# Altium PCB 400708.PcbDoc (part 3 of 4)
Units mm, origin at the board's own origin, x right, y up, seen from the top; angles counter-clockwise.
Board outline 117 x 63.5 mm, 4 copper layers (Top Layer, Mid-Layer 1, Mid-Layer 2, Bottom Layer), stack 1.556 mm thick; 226 components, 168 nets, 912 pads, 2002 vias.
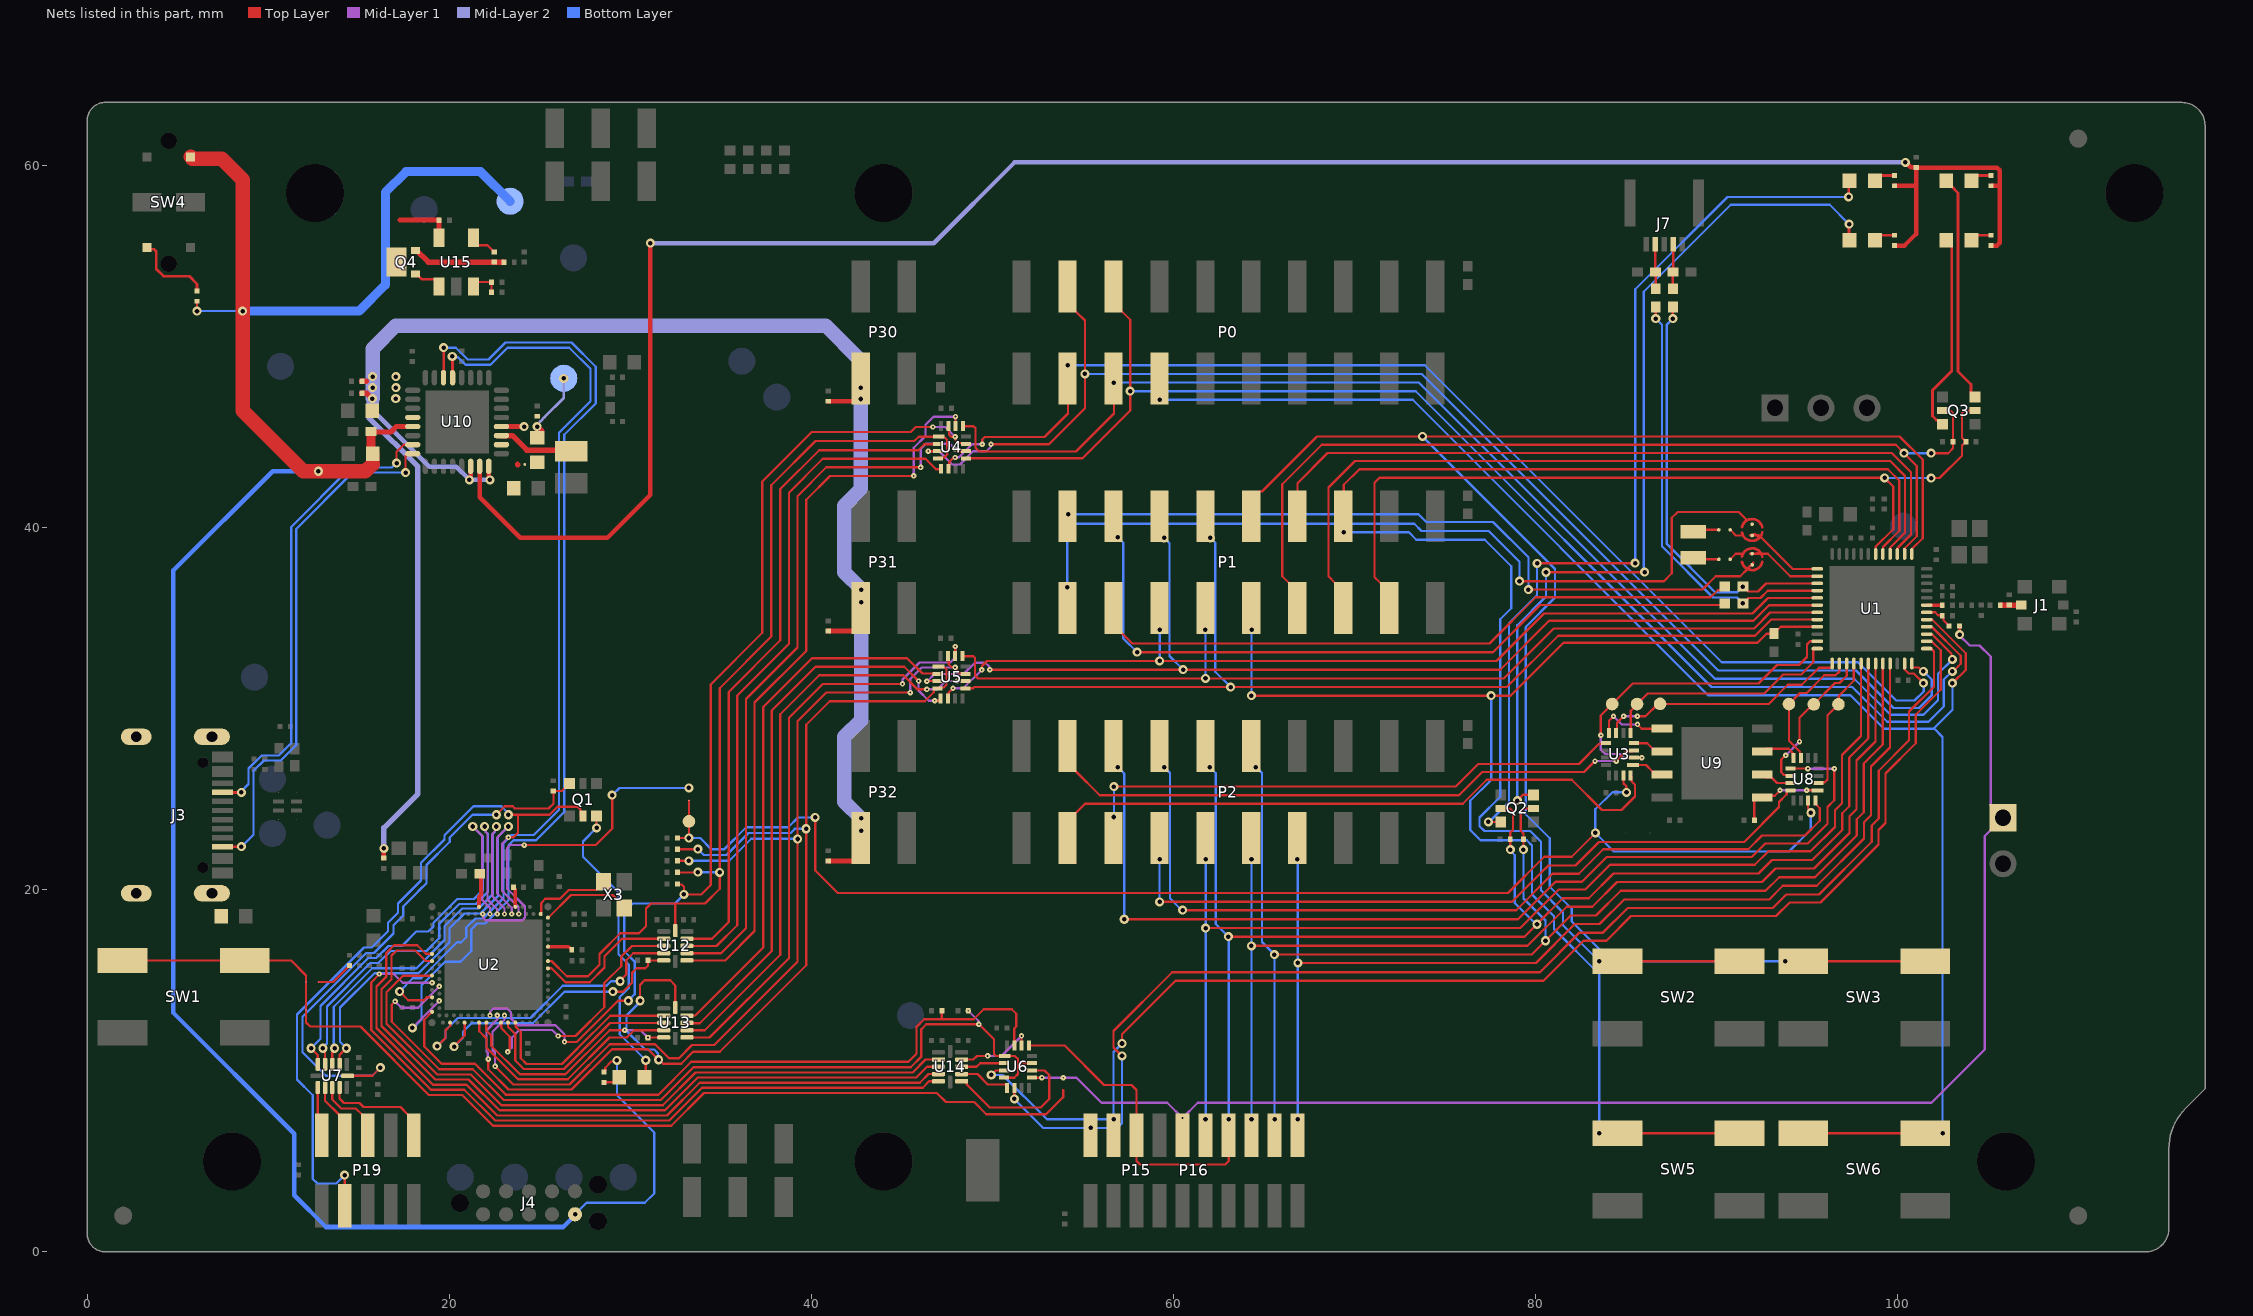
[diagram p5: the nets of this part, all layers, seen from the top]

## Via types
v1: diameter 0.5, hole 0.25, Top Layer to Bottom Layer, tented both sides, 1905 vias
v2: diameter 0.3, hole 0.1, Top Layer to Mid-Layer 1, tented top, 77 vias
v3: diameter 0.3, hole 0.1, Top Layer to Mid-Layer 1, tented both sides, 20 vias

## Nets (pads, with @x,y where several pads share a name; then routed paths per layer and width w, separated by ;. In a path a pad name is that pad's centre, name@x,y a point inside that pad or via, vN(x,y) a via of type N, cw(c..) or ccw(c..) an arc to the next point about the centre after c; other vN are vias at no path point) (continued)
NetC44_1: C44.1 U2.A23 | length 1.1
  Top Layer w0.2: C44.1@23.55,20.154 23.55,20.139 23.66,20.029 U2.A23@23.66,19.064
NetC45_2: C45.2 U2.A13 | length 1.9
  Top Layer w0.225: U2.A13@21.66,19.064 21.66,19.644 21.77,19.754 C45.2@21.77,20.891
NetC59_1: C59.1 J3.SHLD
NetC60_1: C60.1 R3.1 U1.30 | length 1.6
  Top Layer w0.125: U1.30@101.63,35.33 102.102,35.33 102.257,35.175 102.44,35.175 C60.1@102.49,35.125 ; C60.1@102.489,35.117 102.505,35.117 102.561,35.061 102.561,34.99 102.563,34.988 102.563,34.887 R3.1@102.87,34.58
NetC64_2: C64.2 R1.2 R2.2 R19.2 R20.2 U10.31 | length 114.9
  Top Layer w0.25: U10.31@21.692,43.396 21.692,41.686 23.928,39.45 28.749,39.45 31.125,41.826 v1(31.125,55.727) ; R1.2@99.848,55.594 100.403,55.594 101.039,56.23 101.039,58.896 ; R19.2@99.848,58.896 101.039,58.896 ; v1(100.445,60.185) 100.468,60.185 100.743,59.91 101.029,59.91 C64.2@101.039,59.9 ; R2.2@105.182,55.594 105.515,55.594 105.661,55.74 105.661,58.896 ; R20.2@105.182,58.896 105.661,58.896 ; 101.039,58.896 C64.2@101.039,59.9 ; C64.2@101.039,59.9 105.515,59.9 105.661,59.754 105.661,58.896
  Mid-Layer 2 w0.25: v1(31.125,55.727) 46.777,55.727 51.235,60.185 v1(100.445,60.185)
NetC72_1: C72.1 R43.2 U15.3 | length 1.7
  Top Layer w0.125: U15.3@21.35,53.325 21.35,53.338 21.587,53.575 C72.1@22.35,53.575 R43.2@22.35,53.025
NetJ3_A5: J3.A5 U10.23 | length 26.4
  Top Layer w0.125: v1(17.1,43.575) 17.097,43.578 17.097,44.197 17.493,44.593 17.989,44.593 U10.23@17.992,44.596
  Top Layer w0.15: J3.A5@7.485,25.384 v1@8.526,25.384
  Bottom Layer w0.125: v1(8.527,25.383) 8.527,25.451 8.92,25.844 8.92,26.699 9.648,27.428 10.586,27.428 11.275,28.116 11.275,40.046 14.556,43.327 16.839,43.327 17.087,43.575 v1(17.1,43.575)
NetJ3_B5: J3.B5 U10.24 | length 29.1
  Top Layer w0.125: v1(17.594,43.05) 17.591,43.053 17.591,43.935 17.752,44.096 U10.24@17.992,44.096
  Top Layer w0.15: J3.B5@7.485,22.384 v1(8.529,22.384)
  Bottom Layer w0.125: v1(8.529,22.384) 8.538,22.384 9.2,23.046 9.2,26.575 9.775,27.15 10.701,27.15 11.553,28.001 11.553,39.931 14.671,43.05 v1(17.594,43.05)
NetL2_1: L2.1 U1.31 | length 0.9
  Top Layer w0.2: U1.31@101.664,35.73 L2.1@102.521,35.73 ; L2.1@102.521,35.73 L2.1@102.522,35.729
NetL8_2: L8.2 U10.3 | length 4.2
  Top Layer w0.3: U10.3@22.892,45.096 23.492,45.096 24.292,44.296 L8.2@26.749,44.296
NetLD1_1: LD1.1 Q1.6 | length 16.6
  Top Layer w0.125: v1(28.15,23.425) Q1.6@28.15,24.082 ; LD1.1@30.865,9.716 v1(30.865,10.588)
  Top Layer w0.15: LD1.1@30.802,9.652 LD1.1@30.865,9.716
  Bottom Layer w0.125: v1(28.15,23.425) 27.4,22.675 27.4,21.825 29.358,19.867 29.358,16.442 29.925,15.875 29.925,14.575 29.425,14.075 29.425,12.029 v1(30.865,10.588)
NetLD1_2: LD1.2 R5.1 | length 1.4
  Top Layer w0.125: LD1.2@29.12,9.937 LD1.2@29.405,9.652
  Top Layer w0.15: R5.1@28.56,9.367 29.12,9.367 LD1.2@29.405,9.652
NetLD2_1: LD2.1 Q2.6 | length 51.5
  Top Layer w0.125: v1(77.411,23.75) Q2.6@78.1,23.75 ; v1(80.106,38.04) 80.11,38.044 85.519,38.044 v1(85.525,38.05)
  Top Layer w0.15: v1(97.316,58.277) 97.316,59.125 LD2.1@97.371,59.181
  Bottom Layer w0.125: v1(77.411,23.75) 77.45,23.75 78.55,24.85 78.55,34.725 80.106,36.281 v1(80.106,38.04) ; v1(85.525,38.05) 85.525,53.174 90.629,58.278 v1(97.316,58.277)
NetLD2_2: LD2.2 R19.1 | length 1.2
  Top Layer w0.15: LD2.2@98.768,59.181 99.053,59.466 R19.1@99.848,59.466
NetLD3_1: LD3.1 Q3.6 | length 12.6
  Top Layer w0.15: LD3.1@102.705,59.155 103.011,58.849 103.358,58.502 103.358,48.642 104.075,47.925 104.075,47.538 104.076,47.537 104.076,47.449 Q3.6@104.3,47.225
NetLD3_2: LD3.2 R20.1 | length 1.2
  Top Layer w0.15: LD3.2@104.102,59.181 104.387,59.466 R20.1@105.182,59.466
NetLD4_1: LD4.1 Q2.3 | length 49.9
  Top Layer w0.125: v1(79.016,24.934) 79.332,25.25 Q2.3@79.9,25.25 ; v1(80.598,37.544) 86.044,37.544 v1(86.05,37.55)
  Top Layer w0.15: v1(97.341,56.777) 97.341,55.909 LD4.1@97.371,55.879
  Bottom Layer w0.125: v1(79.016,24.934) 79.016,34.618 80.598,36.2 v1(80.598,37.544) ; v1(86.05,37.55) 85.991,37.609 85.991,53.041 90.8,57.85 96.268,57.85 v1(97.341,56.777)
NetLD4_2: LD4.2 R1.1 | length 0.8
  Top Layer w0.15: LD4.2@99.053,56.164 R1.1@99.848,56.164
NetLD5_1: LD5.1 Q3.3 | length 11
  Top Layer w0.15: Q3.3@102.5,45.725 102.275,45.95 102.168,45.95 101.95,46.168 101.95,47.6 103.013,48.663 103.013,55.459 103.011,55.461 103.011,55.573 LD5.1@102.705,55.879
NetLD5_2: LD5.2 R2.1 | length 0.8
  Top Layer w0.15: LD5.2@104.387,56.164 R2.1@105.182,56.164
NetP1_5: P1.5 R33.2 | length 36.7
  Top Layer w0.125: P1.5@56.729,35.877 56.729,34.607 57.734,33.603 77.469,33.603 80.032,36.165 89.69,36.165 90.082,36.557 90.275,36.557 R33.2@90.474,36.755
NetP1_6: P1.6 R34.2 | length 41.6
  Top Layer w0.125: P1.6@56.704,40.64 56.704,39.721 v1(56.95,39.475) ; v1(58.012,33.128) 77.666,33.128 80.268,35.73 90.374,35.73 R34.2@90.474,35.83
  Bottom Layer w0.125: v1(56.95,39.475) 57.25,39.175 57.25,33.89 v1(58.012,33.128)
NetQ1_3: Q1.3 R8.1 U7.12 | length 30.8
  Top Layer w0.125: U7.12@14.4,9.725 15.75,9.725 v1(16.2,10.175) ; v1(22.608,24.15) 23.071,24.613 23.517,24.613 23.641,24.488 25.491,24.488 25.766,24.763 R8.1@25.766,25.449 ; R8.1@25.76,25.455 26.223,25.455 26.477,25.71 Q1.3@26.651,25.71
  Bottom Layer w0.125: v1(16.2,10.175) 15.75,9.725 13.2,9.725 11.9,11.025 11.9,12.983 15.429,16.512 15.848,16.512 16.925,17.589 16.925,18.05 17.462,18.588 17.462,19.081 18.183,19.802 18.371,19.99 18.753,20.372 18.753,21.369 20.043,22.66 20.043,22.893 21.3,24.15 v1(22.608,24.15)
NetQ4_1: Q4.1 U15.1 | length 1.7
  Top Layer w0.15: Q4.1@18.15,54.025 18.2,54.025 18.5,53.725 19.225,53.725 19.45,53.5 U15.1@19.45,53.325
NetQ4_2: Q4.2 R9.1 R38.2 | length 5.1
  Top Layer w0.3: Q4.2@18.15,55.325 18.2,55.325 18.851,54.674 R9.1@23.006,54.674
NetR7_1: R7.1 U2.L31 | length 1.4
  Top Layer w0.187: U2.L31@25.46,16.864 26.597,16.864 26.719,16.743 26.734,16.743 26.775,16.702 R7.1@26.775,16.687
NetR23_1: R23.1 SB8.2 | length 2.1
  Top Layer w0.125: SB8.2@12.8,14.91 13.595,14.91 14.412,15.728 14.412,15.743 14.485,15.815 R23.1@14.5,15.815
NetR35_1: R35.1 SB11.2 TP7.1 U3.15 U8.15 | length 77.3
  Top Layer w0.125: R35.1@32.61,22.864 v1(33.25,22.864) TP7.1@33.25,23.783 SB11.2@33.25,24.933 ; v1(40.225,24) 40.225,21.075 41.478,19.822 78.497,19.822 80.5,21.825 82.025,21.825 83.325,23.125 v1(83.325,23.146) ; U3.15@84.875,26.325 84.875,25.882 85.024,25.733 85.024,25.406 v1(85.044,25.385) ; U8.15@95.075,24.925 95.075,24.506 95.225,24.356 v1(95.225,24.26)
  Bottom Layer w0.125: v1(33.25,22.864) 33.874,22.864 34.502,22.236 35.192,22.236 36.41,23.455 38.737,23.455 39.282,24 v1(40.225,24) ; v1@84.816,25.395 84.27,25.395 83.325,24.45 v1(83.325,23.146) 83.376,23.095 84.346,22.125 94.025,22.125 95.225,23.325 v1(95.225,24.26)
NetR36_1: R36.1 SW4.3 | length 4.5
  Top Layer w0.15: SW4.3@3.321,55.488 3.418,55.392 3.708,55.392 3.825,55.275 3.825,54.3 4.225,53.9 5.646,53.9 6.075,53.471 R36.1@6.075,53.085
NetR38_1: R38.1 U15.4 | length 1.6
  Top Layer w0.125: U15.4@21.35,56.025 21.35,55.825 21.572,55.603 22.126,55.603 R38.1@22.485,55.245
NetSB1_2: SB1.2 SB2.1 SB8.1 SW1.2 | length 59.2
  Top Layer w0.125: SW1.2@1.963,16.097 SW1.2@8.713,16.097 11.277,16.097 12.1,15.273 SB8.1@12.1,14.91 ; 12.1,14.864 SB2.1@12.1,13.364 12.1,12.675 12.325,12.45 15.1,12.45 18.878,8.672 20.728,8.672 22.428,6.972 32.275,6.972 34.086,8.784 46.944,8.784 47.453,8.275 49.011,8.275 49.681,7.605 52.98,7.605 53.925,8.55 SB1.2@53.925,8.925
NetSB3_2: SB3.2 X1.2 | length 1.4
  Top Layer w0.125: X1.2@88.739,39.793 88.833,39.887 SB3.2@90.145,39.887
NetSB4_2: SB4.2 X1.1 | length 1.4
  Top Layer w0.125: X1.1@88.739,38.343 88.82,38.262 SB4.2@90.145,38.262
NetU2_B30: U2.B30 X3.3 | length 4.6
  Top Layer w0.125: U2.B30@25.06,18.664 25.079,18.684 25.079,18.754 25.085,18.76 25.085,19.273 25.315,19.502 26.123,19.502 26.61,19.99 28.127,19.99 28.531,20.394 X3.3@28.531,20.444
NetU2_C31: U2.C31 X3.1 | length 5.1
  Top Layer w0.125: U2.C31@25.46,18.464 25.485,18.464 26.735,19.715 29.027,19.715 29.681,19.061 X3.1@29.681,18.994
NetU4_2: U4.2 U12.10 | length 37.5
  Top Layer w0.125: U12.10@33.14,17.3 34.53,17.3 35.45,18.22 35.45,30.936 38.3,33.786 38.3,42.14 40.45,44.29 45.926,44.29 46.255,44.619 46.984,44.619 U4.2@47.003,44.637
NetU4_5: U4.5 U12.9 | length 37.8
  Top Layer w0.125: U12.9@33.14,16.9 34.775,16.9 35.925,18.05 35.925,30.739 38.775,33.589 38.775,41.944 40.646,43.815 46.322,43.815 46.903,43.233 47.13,43.233 47.16,43.262 U4.5@47.178,43.262
NetU4_10: U4.10 U12.8 | length 40.1
  Top Layer w0.125: U12.8@33.14,16.5 35.016,16.5 36.4,17.884 36.4,30.542 39.25,33.392 39.25,41.747 40.843,43.34 v2@46.05,43.34
  Top Layer w0.127: v2(47.946,44.371) 47.966,44.371 48.1,44.237 U4.10@48.553,44.237
  Mid-Layer 1 w0.125: v2(46.05,43.336) 46.05,44.35 46.341,44.641 47.675,44.641 v2(47.946,44.371)
NetU4_14: U4.14 U12.7 | length 41.4
  Top Layer w0.125: U12.7@33.14,16.1 35.254,16.1 36.875,17.721 36.875,30.346 39.725,33.196 39.725,41.55 41.04,42.865 v2(45.675,42.865) ; U4.14@47.971,45.619 U4.14@47.978,45.612
  Top Layer w0.127: U4.14@47.978,45.612 v2(47.977,46.144)
  Mid-Layer 1 w0.125: v2(45.675,42.865) 45.675,44.425 46.325,45.075 46.325,45.7 46.769,46.144
  Mid-Layer 1 w0.127: 46.769,46.144 v2(47.977,46.144)
NetU5_2: U5.2 U13.10 | length 30.2
  Top Layer w0.125: U13.10@33.14,13.05 33.148,13.058 33.596,13.058 37.35,16.812 37.35,30.101 40.049,32.8 45.3,32.8 46.152,31.948 46.863,31.948 46.875,31.936 U5.2@46.985,31.936
NetU5_5: U5.5 U13.9 | length 31.1
  Top Layer w0.125: U13.9@33.14,12.637 33.847,12.637 37.825,16.616 37.825,29.904 40.246,32.325 45.147,32.325 v2(45.936,31.536) ; v2(46.825,30.45) 47.113,30.45 47.16,30.497 U5.5@47.16,30.561
  Mid-Layer 1 w0.125: v2(45.936,31.536) 45.936,31.014 46.5,30.45 v2(46.825,30.45)
NetU5_10: U5.10 U13.8 | length 31.8
  Top Layer w0.125: U13.8@33.14,12.25 34.131,12.25 38.3,16.419 38.3,29.707 40.443,31.85 45.1,31.85 45.875,31.075 v2(46.4,31.075)
  Top Layer w0.127: v2(48.07,31.536) U5.10@48.535,31.536
  Mid-Layer 1 w0.125: v2(46.4,31.075) 46.975,31.075 47.436,31.536 v2(48.07,31.536)
NetU5_14: U5.14 U13.7 | length 32.6
  Top Layer w0.125: U13.7@33.14,11.84 34.393,11.84 38.775,16.222 38.775,29.51 40.64,31.375 v2(45.05,31.375) ; U5.14@47.953,32.918 U5.14@47.96,32.911
  Top Layer w0.127: U5.14@47.96,32.911 v2@47.96,33.442
  Mid-Layer 1 w0.125: v2(45.05,31.375) 45.05,31.625 45.989,32.564 47.274,32.564 47.275,32.565
  Mid-Layer 1 w0.127: 47.275,32.565 47.69,32.565 47.96,32.835 v2(47.96,33.442)
NetU6_2: U6.2 U14.9 | length 2.4
  Top Layer w0.125: U14.9@48.315,10.225 49.141,10.225 49.341,10.425 U6.2@50.65,10.425
NetU6_5: U6.5 U14.8 | length 2.9
  Top Layer w0.125: U14.8@48.315,9.825 49.189,9.825 49.764,9.25 50.778,9.25 50.825,9.203 U6.5@50.825,9.05
NetU6_10: U6.10 U14.7 | length 8.1
  Top Layer w0.125: U14.7@48.315,9.425 48.536,9.425 48.599,9.363 48.599,9.245 49.864,7.98 51.425,7.98
  Top Layer w0.127: 51.425,7.98 52.682,7.98 53.15,8.448 53.15,9.775 52.9,10.025 U6.10@52.2,10.025
NetU6_14: U6.14 U14.10 | length 4.4
  Top Layer w0.127: U14.10@48.315,10.625 48.961,10.625 49.161,10.825 v2(49.75,10.825) ; U6.14@51.625,11.4 v2@51.625,11.93
  Mid-Layer 1 w0.127: v2(49.75,10.825) 50.518,10.825 v2(51.624,11.931)
NFC1: C17.1 J7.2 R21.2 | length 2.5
  Top Layer w0.125: R21.2@87.604,53.204 C17.1@87.604,54.123 87.629,54.148 J7.2@87.629,55.654
NFC2: C19.2 J7.4 R22.2 | length 2.5
  Top Layer w0.125: J7.4@86.629,55.654 86.629,54.146 C19.2@86.652,54.123 86.661,54.114 R22.2@86.661,53.204
nRF54_RESET: P3.1 P15.10 P16.10 R3.2 SB1.1 U6.9 | length 80.3
  Top Layer w0.125: U6.9@52.2,9.625 U6.9@52.2,9.625 v2(52.752,9.626) ; R3.2@103.435,34.575 103.447,34.563 v1(103.447,34.105)
  Mid-Layer 1 w0.125: v2(52.752,9.626) 53.924,9.626 v2(53.925,9.625) 54.662,9.625 56.047,8.239 59.679,8.239 v2(60.518,7.4) ; v2@60.495,7.377 v2(60.518,7.4) ; v1(103.447,34.105) 103.447,34.053 104,33.5 104.55,33.5 105.16,32.89 105.16,24.668 P3.1@105.845,23.983 104.835,22.972 104.835,11.178 101.896,8.239 61.358,8.239 v2(60.518,7.4)
P0.00: P0.3 U1.23 U4.6 | length 68.2
  Top Layer w0.125: v2(49.45,44.619) 49.45,44.875 49.591,45.016 52.889,45.016 54.189,46.317 54.189,48.235 P0.3@54.164,48.26 v1(54.164,48.975) ; U1.23@100.414,32.496 100.414,32.172 100.633,31.953 100.918,31.953 101.446,31.425 v1(101.45,31.425)
  Top Layer w0.127: U4.6@47.578,43.262 47.624,43.309 47.624,43.624 47.852,43.852 47.92,43.852 v2(47.953,43.885)
  Mid-Layer 1 w0.127: v2(47.953,43.885) 47.964,43.895 48.17,43.895 48.894,44.619 v2(49.45,44.619)
  Bottom Layer w0.125: v1(54.164,48.975) 73.905,48.975 90.305,32.575 97.832,32.575 99.952,30.455 100.956,30.455 101.462,30.961 101.462,31.413 v1(101.45,31.425)
P0.01: P0.4 U1.24 U4.3 | length 75
  Top Layer w0.125: v2(49.939,44.619) 49.941,44.616 53.141,44.616 55.125,46.601 v1(55.125,48.5) 55.125,51.452 54.61,51.967 54.189,52.388 P0.4@54.189,53.222 ; U1.24@100.805,32.505 100.805,32.318 100.84,32.284 101.189,32.284 101.398,32.075 v1(101.45,32.075)
  Top Layer w0.127: v2(46.472,44.237) U4.3@47.003,44.237
  Mid-Layer 1 w0.127: v2(46.472,44.237) 47.063,44.237 47.8,43.5 48.225,43.5 48.95,44.225 49.675,44.225 49.906,44.456 49.906,44.586 v2(49.939,44.619)
  Bottom Layer w0.125: v1(55.125,48.5) 73.736,48.5 90.116,32.12 97.728,32.12 99.8,30.048 101.203,30.048 101.915,30.76 101.915,31.61 101.913,31.612 101.913,31.617 101.454,32.075 v1(101.45,32.075)
P0.02: P0.5 U1.27 U4.13 | length 70.6
  Top Layer w0.125: U4.13@48.378,45.612 48.971,45.612 49.075,45.509 49.075,44.425 49.284,44.216 54.628,44.216 56.729,46.317 P0.5@56.729,48.025 ; P0.5@56.704,48.26 56.725,48.239 v1(56.725,48.025) ; U1.27@101.639,34.121 101.885,34.121 101.913,34.093 101.944,34.093 102.992,33.044 102.992,32.785 v1(103.047,32.73)
  Bottom Layer w0.125: v1(56.725,48.025) 73.568,48.025 89.928,31.665 97.624,31.665 99.622,29.667 101.448,29.667 102.25,30.469 102.25,31.933 v1(103.047,32.73)
P0.03: P0.6 U1.28 U4.9 | length 75.9
  Top Layer w0.125: U4.9@48.553,43.837 54.987,43.837 57.625,46.475 57.625,51.492 56.729,52.388 P0.6@56.729,53.222 ; U1.28@101.63,34.53 101.645,34.516 101.927,34.516 103.51,32.933 103.51,32.491 103.374,32.355 103.094,32.075 v1(103.05,32.075)
  Bottom Layer w0.125: v1(57.625,47.55) 73.399,47.55 89.739,31.21 97.521,31.21 99.444,29.286 101.733,29.286 102.575,30.128 102.575,31.614 103.036,32.075 v1(103.05,32.075)
P0.04: P0.7 SW6.2 U1.29 | length 89.8
  Top Layer w0.125: U1.29@101.639,34.921 101.645,34.916 101.934,34.916 103.785,33.065 103.785,32.15 v1@103.059,31.425
  Top Layer w0.15: v1(59.25,47.075) P0.7@59.25,48.558 ; SW6.2@94.804,6.558 SW6.2@101.554,6.558 v1(102.504,6.558)
  Bottom Layer w0.125: v1(59.25,47.075) 73.231,47.075 89.551,30.755 97.417,30.755 99.266,28.905 102.01,28.905 102.028,28.923 ; v1(102.504,6.558) 102.504,28.447 102.028,28.923 ; v1(103.047,31.425) 103.05,31.422 103.05,29.945 102.028,28.923
P1.00: P1.3 SB5.2 | length 46.3
  Top Layer w0.125: v1(79.134,37.052) v1(79.134,37.052) 87.114,37.053 87.55,37.49 87.55,40.55 87.875,40.875 91.243,40.875 91.703,40.415
  Bottom Layer w0.125: v1(54.15,36.725) 54.15,39.825 54.55,40.225 73.326,40.225 73.726,39.825 77.431,39.825 79.134,38.122 v1(79.134,37.052)
P1.00/XL1: SB3.1 SB5.1 U1.1 | length 5.8
  Top Layer w0.125: SB3.1@90.77,39.887 91.082,39.575 91.483,39.575 ; 91.863,39.591 92.37,39.591 94.231,37.73 U1.1@95.58,37.73 ; SB5.1@91.982,39.575 91.995,39.575 92.059,39.639 92.17,39.639 92.372,39.437
P1.01: P1.4 SB6.2 | length 41.6
  Top Layer w0.125: v1(79.63,36.591) 89.242,36.591 89.981,37.33 91.33,37.33 91.723,37.723 SB6.2@91.911,37.911 ; 91.702,37.735 92.041,38.073 ; 91.735,37.702 91.745,37.713
  Top Layer w0.15: P1.4@54.164,40.64 54.2,40.676 v1(54.2,40.75)
  Bottom Layer w0.125: v1(54.2,40.75) 73.55,40.75 73.975,40.325 77.676,40.325 79.63,38.371 v1(79.63,36.591)
P1.01/XL2: SB4.1 SB6.1 U1.2 | length 5.8
  Top Layer w0.125: SB4.1@90.77,38.262 91.082,38.574 91.483,38.574 ; 91.861,38.57 92.851,38.57 94.091,37.33 U1.2@95.58,37.33 ; SB6.1@91.982,38.574 91.991,38.565 92.027,38.565 92.042,38.549 92.226,38.549 92.38,38.703 ; 92.355,38.728 92.38,38.703 ; 92.381,38.704 92.38,38.703 ; 92.518,38.565 92.413,38.67 92.38,38.703
P1.02/NFC1: R21.1 R33.1 U1.3 | length 23.1
  Top Layer w0.125: v1(87.604,51.554) R21.1@87.604,52.204 ; v1(91.474,36.755) 91.499,36.755 91.774,36.48 92.305,36.48 92.755,36.93 U1.3@95.58,36.93
  Bottom Layer w0.125: v1(87.604,51.554) 87.275,51.225 87.275,39.1 89.937,36.438 91.156,36.438 v1(91.474,36.755)
P1.03/NFC2: R22.1 R34.1 U1.4 | length 23.7
  Top Layer w0.125: v1(86.661,51.554) R22.1@86.661,52.204 ; R34.1@91.384,35.887 91.416,35.887 v1(91.474,35.83) 91.499,35.83 91.711,36.042 91.711,36.052 91.784,36.125 92.441,36.125 92.846,36.53 U1.4@95.58,36.53
  Bottom Layer w0.125: v1(86.661,51.554) 87,51.215 87,38.975 89.82,36.155 91.149,36.155 v1(91.474,35.83)
P1.04: P1.7 U1.5 U5.6 | length 52.3
  Top Layer w0.125: U5.6@47.56,30.561 47.608,30.609 47.608,30.905 v2(47.839,31.136) ; v2(49.425,32.15) 49.439,32.164 49.439,32.364 49.72,32.645 v1(59.257,32.645) 77.866,32.645 80.488,35.267 92.004,35.267 92.858,36.121 U1.5@95.571,36.121
  Mid-Layer 1 w0.125: v2(47.839,31.136) 48.411,31.136 v2(49.425,32.15)
  Bottom Layer w0.125: v1(59.257,32.645) 59.263,32.652 59.263,34.369 v1(59.269,34.375)
P1.05: P1.8 U1.6 U5.3 | length 60.9
  Top Layer w0.125: v2(49.875,32.157) 49.881,32.163 78.066,32.163 80.768,34.865 92.066,34.865 92.922,35.721 U1.6@95.571,35.721 ; P1.8@59.244,40.64 59.244,39.706 v1(59.5,39.45)
  Top Layer w0.127: v2(46.4,31.525) 46.411,31.536 U5.3@46.985,31.536
  Mid-Layer 1 w0.127: v2(46.4,31.525) 46.411,31.525 46.811,31.925 48.425,31.925 49.05,32.55 49.625,32.55 49.842,32.333 49.842,32.19 v2(49.875,32.157)
  Bottom Layer w0.125: v1(59.5,39.45) 59.8,39.15 59.8,32.915 v1(60.552,32.163)
P1.06: P1.9 U1.7 U5.13 | length 53.7
  Top Layer w0.125: U5.13@48.36,32.911 48.954,32.911 49.05,32.815 49.05,31.85 49.22,31.68 v1(61.787,31.68) 78.266,31.68 81.029,34.444 92.096,34.444 92.973,35.321 U1.7@95.571,35.321 ; v1(61.784,34.375) P1.9@61.784,35.56
  Bottom Layer w0.125: v1(61.784,34.375) 61.786,34.374 v1(61.787,31.68) v1(61.787,31.68)
P1.07: P1.10 U1.8 U5.9 | length 58.6
  Top Layer w0.125: U5.9@48.535,31.136 48.961,31.136 49.024,31.2 v1(63.175,31.2) 78.43,31.2 81.274,34.044 92.149,34.044 93.035,34.93 U1.8@95.58,34.93 ; P1.10@61.784,40.64 61.784,39.716 v1(62.05,39.45)
  Bottom Layer w0.125: v1(62.05,39.45) 62.325,39.175 62.325,32.05 v1(63.175,31.2)
P1.08: C41.2 P1.11 SW5.2 U1.9 | length 73.3
  Top Layer w0.125: v1(64.325,30.725) 78.637,30.725 81.558,33.646 92.279,33.646 92.788,34.155 C41.2@93.186,34.155 93.561,34.53 U1.9@95.58,34.53
  Top Layer w0.15: v1(83.535,6.558) SW5.2@84.543,6.558 SW5.2@91.293,6.558
  Bottom Layer w0.125: v1(64.325,30.725) 64.334,30.734 64.334,34.366 v1(64.342,34.375) ; v1(77.567,30.725) 77.567,26.075 76.417,24.925 76.417,23.308 76.983,22.742 79.529,22.742 79.825,22.446 79.825,19.75 81.033,18.542 81.033,17.84 83.535,15.339 v1(83.535,6.558)
P1.09: P1.12 SW3.2 U1.37 | length 97.8
  Top Layer w0.125: P1.12@64.349,40.322 64.349,41.591 64.77,42.011 64.911,42.011 67.95,45.05 100.125,45.05 101.405,43.77 101.405,39.43 100.814,38.839 100.814,38.564 U1.37@100.805,38.555
  Top Layer w0.152: v1(93.804,16.058) SW3.2@94.804,16.058 SW3.2@101.554,16.058
  Bottom Layer w0.125: v1(73.775,45.05) 81.1,37.725 81.1,36.15 79.475,34.525 79.475,25.128 79.478,25.125 79.478,24.742 79.475,24.739 79.475,24.175 80.8,22.85 80.8,20.176 82.024,18.952 82.024,18.251 84.217,16.058 v1(93.804,16.058)
P1.10: P1.13 Q3.2 R11.1 U1.38 | length 53.5
  Top Layer w0.125: P1.13@66.889,36.195 66.419,36.666 66.419,36.933 66.032,37.319 66.032,42.403 68.214,44.585 99.915,44.585 v1(100.375,44.125) 101.08,43.42 101.08,39.531 100.415,38.866 100.415,38.565 U1.38@100.405,38.555 ; v1(101.875,44.125) 102.813,44.125 103.081,44.393 R11.1@103.081,44.763 103.081,46.319 102.939,46.461 102.514,46.461 Q3.2@102.5,46.475
  Bottom Layer w0.125: v1(100.375,44.125) v1(101.875,44.125)
P1.11: P1.14 U1.39 | length 43.3
  Top Layer w0.125: P1.14@66.526,41.956 P1.14@66.864,41.956 ; P1.14@66.864,40.64 P1.14@66.864,41.605 ; P1.14@66.889,40.322 66.889,41.592 66.902,41.605 P1.14@66.902,41.943 ; P1.14@66.889,41.956 P1.14@66.864,41.956 ; U1.39@100.014,38.564 100.014,38.891 100.755,39.632 100.755,43.07 99.695,44.13 68.53,44.13 66.864,42.464 P1.14@66.864,41.956
P1.12: P1.15 U1.40 | length 43.8
  Top Layer w0.125: P1.15@69.429,36.195 68.959,36.666 68.959,36.941 68.582,37.318 68.582,42.223 70.044,43.685 99.614,43.685 100.43,42.869 100.43,39.733 99.615,38.918 U1.40@99.615,38.565
P1.13: P1.16 SW2.2 U1.41 | length 82.6
  Top Layer w0.125: P1.16@69.429,40.64 69.429,42.379 70.289,43.239 99.482,43.239 100.105,42.616 100.105,39.832 99.215,38.942 U1.41@99.215,38.565
  Top Layer w0.15: v1(69.425,39.75) P1.16@69.425,40.318 ; v1(83.535,16.058) SW2.2@84.543,16.058 SW2.2@91.293,16.058
  Bottom Layer w0.125: v1(69.425,39.75) 73.029,39.75 73.436,39.343 77.216,39.343 78.675,37.884 78.675,37.247 78.671,37.243 78.671,35.958 78.675,35.955 78.675,35.55 78.075,34.95 78.075,25.148 76.925,23.998 76.925,23.519 77.194,23.25 79.725,23.25 80.317,22.658 80.317,19.976 81.541,18.752 81.541,18.051 v1(83.535,16.058)
P1.14: P1.17 Q3.5 R27.1 U1.42 | length 48.2
  Top Layer w0.125: P1.17@71.969,35.877 71.969,36.462 71.499,36.933 71.467,36.933 71.125,37.275 71.125,42.49 71.395,42.759 v1@99.294,42.759 ; U1.42@98.815,38.565 98.815,38.966 99.775,39.926 99.775,42.278 v1(99.298,42.755) ; v1(101.875,42.75) 102.34,42.75 103.575,43.985 103.575,44.548 103.703,44.675 103.718,44.675 103.79,44.748 103.79,44.778 103.73,44.838 103.715,44.838 103.575,44.978 103.575,46.339 103.711,46.475 Q3.5@104.3,46.475
  Bottom Layer w0.125: v1(99.298,42.755) 99.303,42.75 v1(101.875,42.75)
P2.00: TP19.1 U1.11 U3.2 | length 18.9
  Top Layer w0.125: v2(83.628,28.54) 83.625,28.543 83.625,29.637 TP19.1@84.253,30.265 85.388,31.4 92.337,31.4 93.362,32.425 94.575,32.425 95.017,32.867 95.017,33.561 95.187,33.73 U1.11@95.58,33.73 ; U3.2@85.45,27.3 v2(85.898,27.3)
  Mid-Layer 1 w0.125: v2(83.628,28.54) 83.628,27.745 83.873,27.5 84.679,27.5 84.879,27.3 v2(85.898,27.3)
P2.00_A: P2.3 U3.16 | length 37
  Top Layer w0.125: P2.3@54.61,21.487 54.19,21.907 54.189,23.812 55.127,24.75 76,24.75 77.326,26.076 82.024,26.076 83.685,24.415 ; 83.697,24.413 84.764,24.413 85.511,25.16 85.511,25.807 85.322,25.996 85.322,26.278 U3.16@85.275,26.325
P2.00_B: U3.1 U9.7 | length 1.8
  Top Layer w0.125: U3.1@85.428,26.9 86.12,26.9 86.493,26.528 86.585,26.435 86.935,26.435 U9.7@87.005,26.365
P2.01: TP20.1 U1.12 U3.5 | length 13.4
  Top Layer w0.125: U3.5@85.275,28.675 85.275,29.887 TP20.1@85.628,30.24 ; TP20.1@85.628,30.265 86.213,30.85 92.649,30.85 93.699,31.9 94.695,31.9 95.364,32.569 95.364,33.295 95.398,33.33 U1.12@95.58,33.33
P2.01_A: P2.4 U3.3 | length 34
  Top Layer w0.125: P2.4@54.164,27.94 54.164,27.013 54.61,26.567 55.952,25.226 75.791,25.226 77.079,26.513 82.701,26.513 v2(83.303,27.115) ; v2(84.478,27.115) 85.015,27.653 85.403,27.653 U3.3@85.45,27.7
  Mid-Layer 1 w0.125: v2(83.303,27.115) v2(84.478,27.115)
P2.01_B: U3.4 U9.6 | length 1.7
  Top Layer w0.125: U3.4@85.45,28.1 86.19,28.1 86.493,27.798 86.655,27.635 U9.6@87.005,27.635
P2.02: TP21.1 U1.13 U3.7 | length 13.9
  Top Layer w0.125: U3.7@84.475,28.675 84.515,28.715 84.515,29.223 v2(84.882,29.59) ; v2(85.65,29.59) 86.098,29.59 86.779,30.272 92.897,30.272 93.95,31.325 94.732,31.325 95.682,32.275 96.371,32.275 96.405,32.31 U1.13@96.405,32.505
  Mid-Layer 1 w0.125: v2(84.882,29.59) v2(85.65,29.59)
P2.02_A: P2.5 U3.9 | length 31.5
  Top Layer w0.125: P2.5@56.729,22.956 56.729,21.908 P2.5@57.15,21.487 ; v1(56.729,25.705) 75.605,25.705 76.851,26.951 82.414,26.951 83.515,28.053 83.853,28.053 U3.9@83.9,28.1
  Bottom Layer w0.125: v1(56.729,24.025) v1(56.729,25.705)
P2.02_B: U3.8 U9.5 | length 4
  Top Layer w0.125: U3.8@84.075,28.675 U3.8@84.075,28.675 84.077,29.339 v2(84.328,29.59) ; v2(85.653,29.14) 85.888,28.905 U9.5@87.005,28.905
  Mid-Layer 1 w0.125: v2(84.328,29.59) 84.778,29.14 v2(85.653,29.14)
P2.03: TP23.1 U1.14 U8.7 | length 7.3
  Top Layer w0.125: TP23.1@93.978,30.227 94.626,30.875 94.998,30.875 95.973,31.85 96.59,31.85 96.805,32.066 U1.14@96.805,32.505 ; TP23.1@94.016,30.265 94.016,28.234 94.628,27.622 94.628,27.33 U8.7@94.683,27.275
P2.03_A: P2.6 U8.9 | length 56.8
  Top Layer w0.125: P2.6@56.704,27.94 56.95,27.694 v1(56.95,26.775) ; v1(57.3,18.375) 79.045,18.375 81.12,20.449 82.586,20.449 83.948,21.812 91.957,21.812 92.707,22.562 95.062,22.562 96.15,23.65 96.15,24.577 96.528,24.955 v2(96.528,26.69) ; U8.9@94.1,26.7 v2(95.064,26.7)
  Top Layer w0.15: P2.6@56.729,26.996 v1(56.95,26.775)
  Mid-Layer 1 w0.125: v2(95.064,26.7) 95.074,26.69 v2(96.528,26.69)
  Bottom Layer w0.125: v1(56.95,26.775) 57.3,26.425 v1(57.3,18.375)
P2.03_B: U8.8 U9.3 | length 2.1
  Top Layer w0.125: U9.3@92.545,27.635 92.7,27.79 94.004,27.79 94.228,27.566 94.228,27.323 U8.8@94.275,27.275
P2.04: TP24.1 U1.15 U8.10 | length 8.3
  Top Layer w0.125: v2(93.837,27.425) 93.81,27.425 93.587,27.203 93.587,26.493 93.74,26.34 94.06,26.34 U8.10@94.1,26.3 ; v2(94.603,28.19) 94.603,29.502 95.351,30.25 TP24.1@95.391,30.25 96.566,31.425 96.805,31.425 97.205,31.825 U1.15@97.205,32.505
  Mid-Layer 1 w0.125: v2(93.837,27.425) v2@94.602,28.19
P2.04_A: P2.7 U8.12 | length 41.2
  Top Layer w0.125: P2.7@59.244,22.86 59.248,22.856 v1(59.248,21.7) ; v1(59.248,19.339) 78.723,19.339 80.271,20.887 80.734,21.35 82.226,21.35 83.526,22.65 91.55,22.65 93.475,24.575 93.475,24.853 93.9,25.277 93.9,25.453 93.947,25.5 U8.12@94.1,25.5
  Bottom Layer w0.125: v1(59.248,19.339) v1(59.248,21.7)
P2.04_B: U8.11 U9.2 | length 1.7
  Top Layer w0.125: U9.2@92.545,26.365 92.707,26.203 93.057,26.203 93.36,25.9 U8.11@94.1,25.9
P2.05: TP25.1 U1.16 U8.2 | length 7.6
  Top Layer w0.125: U8.2@95.65,25.9 95.697,25.947 95.997,25.947 96.15,26.1 96.15,29.65 96.766,30.266 96.766,30.714 97.605,31.554 U1.16@97.605,32.505
P2.05_A: P2.8 U8.16 | length 48.1
  Top Layer w0.125: P2.8@59.244,27.94 59.244,27.031 v1(59.5,26.775) ; v1(60.525,18.875) 78.95,18.875 80.962,20.887 82.404,20.887 83.767,22.25 91.776,22.25 92.526,23 94.905,23 95.725,23.82 95.725,24.514 95.527,24.713 95.522,24.713 95.475,24.76 U8.16@95.475,24.925
  Bottom Layer w0.125: v1(59.5,26.775) 59.819,26.456 59.819,19.531 60.475,18.875 v1(60.525,18.875)
P2.05_B: R39.1 U8.1 U9.1 | length 4.8
  Top Layer w0.125: R39.1@92.107,23.835 92.107,24.933 92.269,25.095 U9.1@92.545,25.095 92.647,25.197 93.234,25.197 v2@93.531,25.494 ; v2(95,25.5) U8.1@95.6,25.5
  Mid-Layer 1 w0.125: v2(93.525,25.5) v2(95,25.5)
P2.06: P2.9 P16.12 U1.17 | length 63.1
  Top Layer w0.125: v1(61.787,7.32) 61.787,6.465 61.788,6.464 P16.12@61.788,6.45 ; v1(61.795,17.887) 79.17,17.887 81.3,20.018 82.764,20.018 84.127,21.38 92.136,21.38 92.886,22.13 95.215,22.13 96.564,23.479 96.564,24.394 96.95,24.78 96.95,27.45 98.005,28.505 U1.17@98.005,32.505 ; v1(61.795,21.7) P2.9@61.795,22.849
  Bottom Layer w0.125: v1(61.787,7.32) 61.795,7.329 61.795,17.894 v1(61.795,21.7)
P2.07: P2.10 P15.6 P16.6 P16.14 Q2.5 R12.1 U1.18 U6.13 | length 93.4
  Top Layer w0.125: U6.13@52.025,11.4 54.01,11.4 56.185,9.225 57.7,9.225 57.978,8.947 P16.6@57.978,6.45 57.978,5.018 58.17,4.826 62.877,4.826 63.07,5.019 63.07,6.439 P16.14@63.058,6.45 63.058,7.309 v1(63.07,7.32) ; P2.10@61.784,27.94 61.784,27.016 v1(62.025,26.775) ; v1(63.051,17.411) 79.411,17.411 v1(80.1,18.1) 80.1,18.117 81.526,19.543 82.961,19.543 84.324,20.906 92.333,20.906 93.083,21.656 95.311,21.656 96.967,23.312 96.967,24.227 97.353,24.613 97.353,27.308 98.405,28.36 U1.18@98.405,32.505 ; Q2.5@78.1,24.5 78.122,24.478 78.629,24.478 78.769,24.339 78.769,23.309 78.627,23.168 78.627,22.792 v1(78.627,22.226)
  Bottom Layer w0.125: v1(62.025,26.775) 62.354,26.446 62.354,18.108 v1(63.051,17.411) ; v1@63.058,17.411 63.065,17.404 63.065,7.325 v1(63.07,7.32) ; v1(78.627,22.226) 78.627,22.162 78.875,21.915 78.875,19.275 80.05,18.1 v1(80.1,18.1)
P2.08: P2.11 P16.16 U1.19 | length 62
  Top Layer w0.125: v1(64.321,16.908) 79.58,16.908 81.739,19.067 83.158,19.067 84.521,20.429 92.53,20.429 93.28,21.179 95.4,21.179 97.367,23.146 97.367,24.061 97.753,24.448 97.753,27.142 98.805,28.194 U1.19@98.805,32.505 ; P16.16@64.328,6.45 v1(64.328,7.32) ; v1(64.328,21.7) P2.11@64.328,22.856
  Bottom Layer w0.125: v1(64.328,7.32) 64.328,16.908 64.325,16.912 64.325,21.696 v1(64.328,21.7)
P2.09: P2.12 P16.18 Q2.2 R10.1 U1.20 | length 75.5
  Top Layer w0.125: P2.12@64.324,27.94 64.324,27.035 v1(64.575,26.785) ; v1(65.596,16.427) 79.81,16.427 v1(80.57,17.187) 81.968,18.586 83.358,18.586 84.72,19.948 92.729,19.948 93.479,20.698 95.462,20.698 97.767,23.003 97.767,23.896 98.153,24.282 98.153,26.976 99.205,28.029 U1.20@99.205,32.505 ; P16.18@65.598,6.45 65.601,6.453 v1(65.601,7.32) ; v1(79.35,22.226) 79.355,22.23 R10.1@79.355,22.798 79.355,23.109 79.204,23.259 79.204,24.322 79.382,24.5 Q2.2@79.9,24.5
  Bottom Layer w0.125: v1(64.575,26.785) 64.908,26.451 64.908,17.115 v1(65.596,16.427) ; v1@65.598,16.427 65.601,16.424 v1(65.601,7.32) ; v1(79.35,22.226) 79.35,19.525 80.57,18.305 v1(80.57,17.187)
P2.10: P2.13 P16.20 U1.21 | length 60.8
  Top Layer w0.125: P16.20@66.868,6.45 66.875,6.457 66.875,7.309 v1(66.886,7.32) ; v1(66.868,21.7) P2.13@66.868,22.856 ; v1(66.886,15.963) 80.046,15.963 82.191,18.108 83.555,18.108 84.918,19.471 92.927,19.471 93.677,20.221 95.551,20.221 98.167,22.837 98.167,23.73 98.553,24.116 98.553,26.811 99.605,27.863 U1.21@99.605,32.505
  Bottom Layer w0.125: v1(66.868,21.7) 66.877,21.691 66.877,15.958 66.886,15.949 v1(66.886,7.32)
P5V0: C24.2 C26.2 C52.2 C55.2 C56.2 C62.2 C69.1 C70.2 P30.1 P31.1 P32.1 Q4.3 R4.2 R40.2 TP10.1 U10.4 U10.20 U10.30 U10.32 U15.5 | length 113.3
  Top Layer w0.25: R40.2@16.394,21.754 v1(16.394,22.288) ; v1(21.125,42.65) 21.125,42.718 21.184,42.777 21.184,43.388 U10.30@21.192,43.396 ; U10.32@22.192,43.396 22.195,43.393 22.195,42.772 22.25,42.718 v1(22.25,42.65) ; v1(24.867,45.596) 24.907,45.596 25.138,45.365
  Top Layer w0.27: 17.273,57 C69.1@19.45,57 U15.5@19.45,56.025 ; C52.2@40.95,21.59 42.361,21.59 42.759,21.988 v1(42.759,23.254) ; C55.2@40.95,34.29 42.361,34.29 42.734,34.663 P31.1@42.734,35.56 ; C62.2@40.95,46.99 42.75,46.99 v1(42.75,47.116) v1(42.75,47.75)
  Top Layer w0.3: C70.2@15.185,47.425 15.467,47.425 15.755,47.137 v1(15.757,47.137) ; R4.2@15.185,48.091 15.43,48.091 ; U10.4@22.892,45.596 v1@24.038,45.596
  Mid-Layer 2 w0.15: 25.025,45.875 25.04,45.875 25.278,46.113 26.334,47.169 v1(26.334,48.26)
  Mid-Layer 2 w0.25: v1(15.757,47.137) 15.763,47.137 16,46.9 16,46.275 18.9,43.375 20.4,43.375 v1(21.125,42.65) v1(22.25,42.65)
  Mid-Layer 2 w0.3: v1(15.757,47.137) 15.757,47.083 15.6,46.926 15.6,46.05 18.275,43.375 18.275,25.306 16.394,23.425 v1(16.394,22.288)
  Mid-Layer 2 w0.8: v1@15.775,47.155 v1(15.775,47.746) v1(15.775,48.355) 15.775,49.9 17.05,51.175 40.807,51.175 42.75,49.232 v1(42.75,47.75) v1(42.75,47.116) 42.75,42.146 41.829,41.225 41.829,37.55 42.759,36.62 v1(42.759,36.569) v1(42.759,35.877) 42.759,29.38 41.829,28.45 41.829,24.875 v1(42.759,23.945) v1(42.759,23.254)
  other v1: 24.142,45.596 17.055,47.137 17.056,47.746 17.056,48.355
PVSS1: C24.1 C27.1 NT2.2 U10.2 | length 0
  Top Layer w0.3: 23.78,43.496 23.78,43.508 23.792,43.496
QSPI_CTRL: SB11.1 U2.B14 | length 19.4
  Top Layer w0.125: v2(24.15,22.475) 28.1,22.475 29.013,23.388 v1(29.013,25.234)
  Mid-Layer 1 w0.125: v2(21.86,18.664) 21.887,18.638 21.887,18.463 22.025,18.325 24.05,18.325 24.2,18.475 24.2,19.075 23.217,20.058 23.217,22.317 23.375,22.475 v2(24.15,22.475)
  Bottom Layer w0.125: v1(29.013,25.234) 29.412,25.633 v1(33.25,25.633)
RF: C61.2 J1.1 L4.2 | length 1.1
  Top Layer w0.3: L4.2@105.741,35.73 C61.2@106.2,35.73 J1.1@106.845,35.73
SWD0_CLK: U2.B18 U7.4 | length 24.1
  Top Layer w0.125: v1(13.025,11.25) 13.025,11.149 13.15,11.024 U7.4@13.15,10.365
  Mid-Layer 1 w0.125: v1(21.958,23.5) 22.019,23.439 22.019,23.192 22.116,23.095 22.116,19.472 22.66,18.928 v2(22.66,18.664)
  Bottom Layer w0.125: v1(13.025,11.25) 13.025,11.286 13.25,11.511 13.25,13.553 15.652,15.955 16.091,15.955 16.761,16.625 18.75,16.625 19.45,17.325 19.45,18.114 20.561,19.225 21.487,19.225 22.153,19.891 22.153,23.089 22.03,23.212 22.03,23.428 v1(21.958,23.5)
SWD0_CLK_EXT: P19.4 U7.8 | length 3.1
  Top Layer w0.125: U7.8@13.15,9.085 13.15,8.354 13.917,7.588 13.917,6.768 P19.4@14.234,6.45
SWD0_IO: U2.B16 U7.5 | length 24.3
  Top Layer w0.125: v1(12.375,11.25) 12.375,11.246 12.75,10.871 U7.5@12.75,10.365
  Mid-Layer 1 w0.125: v1(21.308,23.5) 21.308,23.496 21.833,22.971 21.833,19.438 22.26,19.01 v2(22.26,18.664)
  Bottom Layer w0.125: v1(12.375,11.25) 12.375,11.254 12.893,11.772 12.893,13.585 15.538,16.23 15.977,16.23 16.647,16.9 17.397,16.9 18.19,17.694 18.849,17.694 19.137,17.982 19.137,18.19 20.447,19.5 21.373,19.5 21.878,20.005 21.878,22.93 21.771,23.038 21.767,23.038 21.308,23.496 v1(21.308,23.5)
SWD0_IO_EXT: P19.2 U7.7 | length 2.7
  Top Layer w0.125: U7.7@12.75,9.085 12.75,6.664 P19.2@12.964,6.45 P19.2@12.975,6.461
SWD0_RESET: U2.B22 U7.2 | length 24.7
  Top Layer w0.125: U7.2@13.95,10.365 13.95,10.871 14.325,11.246 v1(14.325,11.25)
  Mid-Layer 1 w0.125: v1(23.275,23.5) 22.666,22.891 22.666,19.811 23.46,19.017 v2(23.46,18.664)
  Bottom Layer w0.125: v1(14.325,11.25) 14.325,11.254 13.975,11.604 13.975,13.5 15.875,15.4 18.314,15.4 20.025,17.111 20.025,17.875 20.849,18.699 21.738,18.699 22.703,19.663 22.703,22.928 v1(23.275,23.5)
SWD0_RESET_EXT: P19.10 U7.10 | length 6
  Top Layer w0.125: 13.95,8.475 14.2,8.225 15.05,8.225 15.275,8 17.314,8 17.737,7.578 17.737,6.758 P19.10@18.044,6.45 ; 13.95,8.5 U7.10@13.95,9.085
SWD0_SEL: P19.3 Q1.5 U2.B24 | length 42.2
  Top Layer w0.125: v2(23.275,22.9) 23.554,22.9 23.804,23.15 23.804,24.15 ; v1(23.275,24.15) 23.804,24.15 ; Q1.5@27.263,24.047 27.263,24.433 27.101,24.596 25.987,24.596 25.542,24.15 23.804,24.15
  Top Layer w0.15: P19.3@14.234,2.55 v1(14.234,4.246)
  Mid-Layer 1 w0.125: v2(23.275,22.9) 22.941,22.566 22.941,19.943 23.835,19.049 23.835,18.689 v2(23.86,18.664)
  Bottom Layer w0.125: v1(14.234,4.246) 13.763,3.775 12.725,3.775 12.475,4.025 12.475,8.65 11.6,9.525 11.6,13.113 15.303,16.816 15.722,16.816 16.621,17.715 16.621,18.176 17.175,18.73 17.175,19.24 18.455,20.519 18.455,21.496 19.743,22.784 19.743,23.018 21.35,24.625 22.882,24.625 23.275,24.232 v1(23.275,24.15)
SWD0_SWO: U2.B20 U7.3 | length 24.1
  Top Layer w0.125: U7.3@13.55,10.365 13.55,11.024 13.675,11.149 v1(13.675,11.25)
  Mid-Layer 1 w0.125: v1(22.608,23.5) 22.536,23.428 22.536,23.236 22.391,23.091 22.391,19.655 23.06,18.986 v2(23.06,18.664)
  Bottom Layer w0.125: v1(13.675,11.25) 13.625,11.3 13.625,13.539 15.761,15.675 18.2,15.675 19.75,17.225 19.75,17.989 20.735,18.974 21.625,18.974 22.428,19.777 22.428,23.105 22.536,23.214 22.536,23.428 v1(22.608,23.5)
SWD0_SWO_EXT: P19.6 U7.9 | length 3.9
  Top Layer w0.125: U7.9@13.55,9.085 13.55,8.425 14.05,7.925 14.849,7.925 15.2,7.574 15.2,6.754 P19.6@15.504,6.45
SWD3_CLK: U2.R1 U14.3 | length 40.4
  Top Layer w0.125: U2.R1@19.06,16.064 18.715,16.064 18.124,16.655 17.105,16.655 16.825,16.375 16.825,15.065 16.266,14.507 16.266,12.484 19.229,9.521 21.079,9.521 22.779,7.821 31.923,7.821 33.735,9.632 45.811,9.632 46.403,10.225 U14.3@47.035,10.225
SWD3_CTRL: R31.2 U2.AB2 U6.1 U6.4 U6.11 | length 48.1
  Top Layer w0.125: v2(17.02,13.84) 16.831,13.651 16.831,12.719 19.464,10.086 21.314,10.086 23.014,8.386 31.689,8.386 33.5,10.198 44.319,10.198 45.497,10.198 46.091,10.792 46.091,12.065
  Top Layer w0.127: 46.091,11.97 46.091,12.065 46.091,12.306 46.363,12.577 v2(49.267,12.577) 50.1,11.744 50.1,10.925 50.2,10.825 U6.1@50.7,10.825 51.25,10.825 51.425,10.65 51.425,10.425 ; U6.4@50.65,9.625 U6.4@50.65,9.625 51.225,9.625 51.425,9.825 51.425,10.425 ; U6.11@52.2,10.425 51.425,10.425
  Mid-Layer 1 w0.125: v2(48.68,13.325) 49.234,12.771 49.234,12.611 v2(49.267,12.577)
  Mid-Layer 1 w0.127: v2(17.02,13.84) 17.366,13.493 18.289,13.493 v3(19.46,14.664)
SWD3_IO: U2.N1 U14.4 | length 41.3
  Top Layer w0.125: U2.N1@19.06,16.464 18.711,16.464 18.238,16.937 16.961,16.937 16.537,16.514 16.537,15.213 15.987,14.663 15.987,12.363 19.112,9.238 20.962,9.238 22.662,7.538 32.04,7.538 33.852,9.349 46.003,9.349 46.478,9.825 U14.4@47.035,9.825
SWD3_RESET: U2.AA1 U14.5 | length 40.7
  Top Layer w0.125: v2(16.145,15.352) 16.145,15.337 15.696,14.888 15.696,12.254 18.995,8.955 20.845,8.955 22.545,7.255 32.158,7.255 33.969,9.066 46.16,9.066 46.519,9.425 U14.5@47.035,9.425
  Mid-Layer 1 w0.125: v2(16.145,15.352) 16.948,15.352 17.436,14.864 v2(19.06,14.864)
SWD3_SWO: U2.W1 U14.2 | length 38
  Top Layer w0.125: U2.W1@19.06,15.264 19.056,15.26 17.46,15.26 16.544,14.344 16.544,12.606 19.346,9.804 21.196,9.804 22.896,8.104 31.806,8.104 33.617,9.915 45.609,9.915 46.319,10.625 U14.2@47.035,10.625
SWDCLK: P15.4 P16.4 U1.26 U6.3 | length 73.6
  Top Layer w0.125: v1(49.95,9.775) v1(49.95,9.775) 50.201,10.025 U6.3@50.65,10.025 ; P16.4@56.708,6.45 v1(56.708,7.325) ; v1(57.175,11.513) 57.175,12.025 60.128,14.978 80.453,14.978 82.662,17.187 83.937,17.187 85.299,18.55 93.308,18.55 94.058,19.3 95.764,19.3 98.969,22.505 98.969,23.304 99.355,23.69 99.355,26.43 101.025,28.1 101.025,29.675 102.4,31.05 102.4,33.23 101.938,33.693 101.913,33.693 101.885,33.72 U1.26@101.64,33.72
  Bottom Layer w0.125: v1(49.95,9.775) 50.575,9.775 53.025,7.325 v1(56.708,7.325) 56.708,11.046 v1(57.175,11.513)
SWDIO: P15.2 P16.2 U1.25 U6.6 | length 71.2
  Top Layer w0.125: v1(51.225,8.448) U6.6@51.225,9.05 ; v1(57.175,10.825) 56.71,11.29 56.71,12.206 59.957,15.453 62.906,15.453 80.261,15.453 82.445,17.637 83.75,17.637 85.113,19 93.122,19 93.872,19.75 95.676,19.75 98.589,22.662 98.589,23.555 98.975,23.942 98.975,26.586 100.65,28.261 100.65,29.848 102.028,31.226 102.028,33.169 101.867,33.33 U1.25@101.63,33.33
  Bottom Layer w0.125: v1(51.225,8.448) 52.823,6.85 v1(55.438,6.85) 56.925,6.85 57.175,7.1 v1(57.175,10.825)
SWO_CTRL: R17.1 U2.AJ1 U6.15 | length 41.1
  Top Layer w0.125: U2.AJ1@19.06,13.264 18.627,12.831 18.627,11.348 19.588,10.387 21.438,10.387 23.138,8.687 31.564,8.687 33.376,10.498 45.373,10.498 45.815,10.94 45.815,12.42 46.249,12.853 47.231,12.853 ; R17.1@47.224,13.325 47.224,12.86 47.231,12.853 ; U6.15@51.225,11.4 51.225,12.344 51.335,12.454 51.335,13.15 51.085,13.4 49.538,13.4 48.991,12.853 47.231,12.853
TWI0_SCL: U2.AF2 U10.14 | length 55.6
  Top Layer w0.15: U10.14@19.692,48.296 19.699,48.303 v1@19.699,49.949
  Mid-Layer 1 w0.125: v1@17.975,12.376 v3@19.454,13.855
  Bottom Layer w0.125: v1(17.975,12.375) 18.025,12.375 18.475,12.825 18.475,14.725 19.775,16.025 20.625,16.025 21.225,16.625 21.225,17.812 21.548,18.135 21.993,18.135 23.288,19.431 23.288,22.461 23.564,22.737 24.799,22.737 26.366,24.304 26.366,45.137 28.1,46.871 28.1,48.903 26.765,50.237 23.112,50.237 22.175,49.3 21.025,49.3 20.375,49.95 v1(19.7,49.95)
  other v3: 19.46,13.864
TWI0_SDA: U2.AE1 U10.13 | length 52.1
  Top Layer w0.125: v1(17.269,14.385) 17.748,13.906 18.603,13.906 18.761,14.064 U2.AE1@19.059,14.064
  Top Layer w0.15: U10.13@20.192,48.296 v1@20.192,49.478
  Bottom Layer w0.125: v1(17.269,14.385) 18,15.116 18.458,15.116 20.442,17.1 20.675,17.1 20.952,17.377 20.952,17.916 21.46,18.424 21.874,18.424 23,19.55 23,22.58 23.445,23.025 24.679,23.025 26.077,24.423 26.077,45.257 27.811,46.991 27.811,48.783 26.645,49.95 23.233,49.95 22.295,49.012 20.905,49.012 20.493,49.424 20.226,49.424 v1(20.175,49.475)
UART0_CTRL: R14.2 U2.R31 U4.1 U4.4 U12.12 | length 52.4
  Top Layer w0.125: U2.R31@25.46,16.064 25.664,16.064 26.504,15.225 27.671,15.225 28.312,15.867 28.312,16.451 29.461,17.6 30.488,17.6 30.875,17.988 30.875,18.975 31.151,19.251 34.136,19.251 34.95,20.065 v1(34.95,20.964) 34.95,31.143 37.8,33.993 37.8,42.347 40.243,44.79 45.704,44.79 45.952,45.037 U4.1@47.053,45.037 ; U12.12@32.5,17.75 32.5,19.239 ; R14.2@32.61,20.964 33.737,20.964 v1(33.75,20.977) ; U4.4@47.003,43.837 47.05,43.885 47.347,43.885 47.525,44.063 47.525,44.851 47.386,44.99 47.1,44.99 U4.1@47.077,45.013
  Bottom Layer w0.125: v1(33.75,20.977) 34.937,20.977 v1(34.95,20.964)
UART0_CTS: R32.1 U2.AL9 U12.5 | length 15.8
  Top Layer w0.125: v1(20.279,11.34) 20.279,11.372 20.742,11.834 20.742,11.836 20.86,11.954 U2.AL9@20.86,12.664
  Top Layer w0.127: v1(29.05,14.375) 29.611,14.375 30.1,14.864 30.1,15.402 30.363,15.664 30.843,15.664 30.985,15.807 R32.1@30.985,16.1 U12.5@31.86,16.1
  Bottom Layer w0.125: v1(20.279,11.34) 20.775,11.836 20.775,12.167 21.233,12.625 24.625,12.625 26.375,14.375 v1(29.05,14.375)
UART0_HWFC: R13.2 U2.AK16 U4.11 U4.15 | length 58.9
  Top Layer w0.125: v2(26.375,11.6) 27.059,11.6 27.124,11.665 29.334,13.875 v1(29.9,13.875) ; R13.2@32.61,20.325 32.645,20.29 32.859,20.29 32.975,20.174 v1(32.975,19.747) 33.926,19.747 34.45,20.271 34.45,31.35 37.3,34.2 37.3,42.554 40.035,45.29 45.504,45.29 45.782,45.568 v2(46.728,45.568) ; U4.15@47.578,45.612 47.622,45.568 47.622,45.148 47.734,45.036 47.946,45.036 47.987,44.994 47.987,44.863 48.168,44.682 48.508,44.682 U4.11@48.553,44.637
  Mid-Layer 1 w0.125: v2(22.26,13.064) 22.27,13.074 22.27,13.282 22.421,13.433 23.23,13.433 23.422,13.241 23.422,13.215 23.423,12.89 23.787,12.525 25.875,12.525 26.375,12.025 v2(26.375,11.6) ; v2(46.728,45.568) 47.413,45.568 v2(47.953,45.028)
  Bottom Layer w0.125: v1(29.9,13.875) 29.9,13.879 30.25,14.229 30.25,16.038 29.675,16.613 29.675,18.8 30.126,19.251 32.479,19.251 v1(32.975,19.747)
UART0_RTS: U2.AL5 U12.4 | length 17
  Top Layer w0.125: v1(19.34,11.366) 19.797,11.823 19.797,12.23 20.059,12.492 U2.AL5@20.06,12.664 U2.AL5@20.06,12.664 ; v1(29.45,14.95) 29.45,14.98 29.788,15.318 29.788,16.113 30.175,16.5 U12.4@31.86,16.5
  Bottom Layer w0.125: v1(19.34,11.366) 19.797,11.823 19.797,12.246 20.477,12.926 24.5,12.926 26.274,14.7 27.124,14.7 28.691,14.7 28.941,14.95 v1(29.45,14.95)
UART0_RxD: U2.AL19 U12.3 | length 14.6
  Top Layer w0.125: U2.AL19@22.86,12.664 22.879,12.645 22.879,12.365 23.353,11.891 23.353,11.213 23.237,11.097 v2(23.237,11.05) ; v2(26.025,11.925) 26.984,11.925 27.124,12.065 28.578,13.519 28.578,14.851 29.513,15.785 29.513,16.226 29.513,16.312 30.1,16.9 U12.3@31.86,16.9
  Mid-Layer 1 w0.125: v2(23.237,11.05) 23.46,11.273 23.46,11.834 23.883,12.257 25.693,12.257 v2(26.025,11.925)
UART0_TxD: U2.U31 U12.2 | length 8.1
  Top Layer w0.125: U2.U31@25.46,15.664 25.664,15.664 26.429,14.9 27.775,14.9 28.587,15.712 28.587,16.337 29.55,17.3 U12.2@31.86,17.3
UART1_CTRL: R16.2 U2.AK18 U5.1 U5.4 U13.12 | length 64.9
  Top Layer w0.125: v3(22.163,10.65) 22.163,10.088 23.281,8.969 26.764,8.969 28.995,11.2 30.989,11.2 v1(31.575,10.614) 31.621,10.614 31.836,10.4 32.827,10.4 33.477,11.05 34.946,11.05 39.725,15.829 v1(39.725,23.375) 39.725,29.117 41.033,30.425 46.275,30.425 46.773,30.923 46.773,31.089 46.82,31.136 U5.4@46.947,31.136 ; v1(30.55,13.875) 30.55,14.75 30.801,15.001 32.214,15.001 32.5,14.715 U13.12@32.5,13.5 ; R16.2@32.61,22.237 33.737,22.237 v1(33.75,22.25) ; U5.4@46.985,31.136 47.033,31.184 47.33,31.184 47.475,31.329 47.475,32.182 47.369,32.289 47.083,32.289 U5.1@47.035,32.336
  Top Layer w0.127: U5.4@46.947,31.136 U5.4@46.985,31.136
  Mid-Layer 1 w0.125: v3(22.163,10.65) 22.143,10.67 22.143,10.995 22.061,11.076 22.061,12.235 22.66,12.834 v2(22.66,13.064)
  Bottom Layer w0.125: v1(30.55,13.875) 30.55,13.799 29.806,13.055 29.806,12.2 30.831,11.175 31.328,11.175 31.548,10.956 31.548,10.642 v1(31.575,10.614) ; v1(33.75,22.25) 34.075,21.925 35.328,21.925 36.547,23.145 38.871,23.145 39.103,23.377 39.723,23.377 v1(39.725,23.375)
UART1_CTS: R56.1 U2.AL15 U13.5 | length 12.8
  Top Layer w0.125: U2.AL15@22.06,12.664 22.06,12.226 22.336,11.95 22.336,11.389 23.916,9.809 26.437,9.809 28.878,12.25 v2(29.7,12.25) ; v2(30.985,11.84) 31.85,11.84 U13.5@31.86,11.85
  Mid-Layer 1 w0.125: v2(29.7,12.25) 30.575,12.25 v2(30.985,11.84)
UART1_HWFC: R15.2 U2.AK20 U5.11 U5.15 | length 56.2
  Top Layer w0.125: v3(22.54,10.25) 23.546,9.244 26.65,9.244 28.881,11.475 31.375,11.475 32.15,10.7 32.7,10.7 33.425,11.425 34.65,11.425 39.25,16.025 v1(39.25,22.81) 39.25,29.314 40.836,30.9 v2(45.475,30.9) ; R15.2@32.61,21.605 v1(33.25,21.605) ; U5.15@47.56,32.911 47.605,32.867 47.605,32.446 47.744,32.307 47.935,32.307 47.987,32.255 47.987,32.199 48.202,31.984 48.488,31.984 U5.11@48.535,31.936
  Mid-Layer 1 w0.125: v3(22.54,10.25) 22.54,11.01 22.4,11.15 22.4,12.162 23.06,12.822 v2(23.06,13.064) ; v2(45.475,30.9) 45.475,31.646 46.118,32.289 v2(47.953,32.289)
  Bottom Layer w0.125: v1(33.25,21.605) 35.481,21.605 36.697,22.821 39.238,22.821 v1(39.25,22.81)
UART1_RTS: U2.AL13 U13.4 | length 13.2
  Top Layer w0.125: U2.AL13@21.66,12.664 21.66,12.195 22.061,11.793 22.061,11.275 23.802,9.534 26.551,9.534 28.857,11.84 29.815,11.84 30.225,12.25 U13.4@31.86,12.25
UART1_RxD: U2.AL21 U13.3 | length 11.7
  Top Layer w0.125: U2.AL21@23.26,12.664 23.26,12.431 23.658,12.033 23.658,10.575 24.124,10.109 26.348,10.109 28.889,12.65 U13.3@31.86,12.65
UART1_TxD: U2.AL23 U13.2 | length 11.2
  Top Layer w0.125: U2.AL23@23.66,12.664 23.671,12.654 23.671,12.457 23.962,12.165 23.962,10.697 24.276,10.384 26.234,10.384 27.063,11.213 27.124,11.274 28.9,13.05 U13.2@31.86,13.05
VBUS: C23.2 C54.1 J4.5 R5.2 R36.2 SW4.4 TP8.1 U10.21 | length 132.1
  Top Layer w0.125: v1(6.075,51.975) R36.2@6.075,52.515 ; R5.2@28.56,9.937 28.624,10.001 28.624,10.174 28.966,10.516 29.216,10.516 v1(29.275,10.575)
  Top Layer w0.3: C23.2@15.684,45.313 15.702,45.295 16.78,45.295 17.081,45.596 U10.21@17.992,45.596
  Top Layer w0.5: C23.2@15.684,45.313 15.684,44.191 C54.1@15.775,44.1
  Top Layer w0.75: 15.775,43.525 C54.1@15.775,44.1
  Top Layer w0.8: SW4.4@5.721,60.488 5.816,60.393 7.432,60.393 8.6,59.225 v1(8.6,51.969) 8.6,46.471 11.946,43.125 v1(12.775,43.125) 15.375,43.125 15.775,43.525
  Bottom Layer w0.125: v1(6.075,51.975) 8.594,51.975 v1(8.6,51.969) ; v1(26.958,2.074) 27.593,2.709 30.808,2.709 31.328,3.23 31.328,6.597 29.275,8.65 v1(29.275,10.575)
  Bottom Layer w0.25: v1(12.775,43.125) 10.25,43.125 4.775,37.65 4.775,13.2 11.452,6.523 11.452,3.123 13.2,1.375 26.3,1.375 26.958,2.033 v1(26.958,2.074)
  Bottom Layer w0.5: v1(8.6,51.969) 15.024,51.969 16.482,53.427 16.482,58.532 17.625,59.675 21.736,59.675 TP8.1@23.372,58.039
